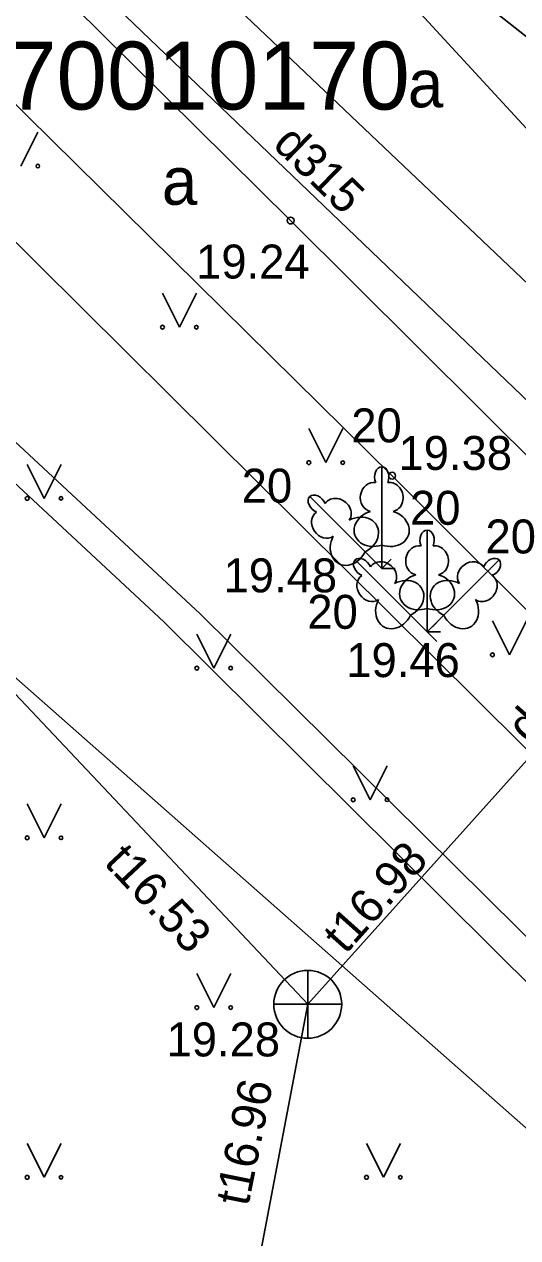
# Model space of a CAD drawing. Extents: x 532933 to 533143, y 328014 to 328163.
# Drawn here: x 533014.71 to 533021.98, y 328109.11 to 328126.98 of the extents above; entities that cross this region are included whole.
import ezdxf

# ---------------------------------------------------------------- set-up
doc = ezdxf.new("R2010")
doc.units = 0
for name, color, linetype in [('APGR_SARK_####_####_#', 7, 'Continuous'), ('CELI_CAPM_####_####_#', 7, 'Continuous'), ('CELI_CMAL_####_####_#', 7, 'Continuous'), ('CELI_CSEG_####_TKST_#', 7, 'Continuous'), ('LKAN_VADP_PAST_####_#', 7, 'Continuous'), ('LKAN_VADP_PAST_TKST_#', 7, 'Continuous'), ('RELJ_AATZ_####_TKST_#', 7, 'Continuous'), ('RELJ_ELEM_####_####_#', 7, 'Continuous'), ('ROBZ_PROJ_####_####_#', 7, 'Continuous'), ('ROBZ_PROJ_####_TKST_#', 7, 'Continuous'), ('ROBZ_UZMR_####_####_#', 7, 'Continuous'), ('SAKK_KKAN_####_####_#', 7, 'Continuous'), ('SAKT_VADV_PKAB_####_#', 7, 'Continuous'), ('SILT_VADP_UDEN_####_#', 7, 'Continuous'), ('SKAN_ELEM_####_####_#', 7, 'Continuous'), ('SKAN_ELEM_PAST_TKST_#', 7, 'Continuous'), ('SKAN_VADP_PAST_####_#', 7, 'Continuous'), ('SKAN_VADP_PAST_TKST_#', 7, 'Continuous'), ('TERT_DIAM_####_TKST_#', 7, 'Continuous'), ('TERT_ELEM_####_####_#', 7, 'Continuous'), ('UDTK_VADP_UDEN_####_#', 7, 'Continuous')]:
    doc.layers.add(name, color=color, linetype=linetype)

msp = doc.modelspace()

# ---------------------------------------------------------------- linework, layer by layer
at = {"layer": 'APGR_SARK_####_####_#'}
msp.add_line((533025.763, 328107.492), (532984.275, 328144.093), dxfattribs=at)
at = {"layer": 'CELI_CAPM_####_####_#'}
msp.add_lwpolyline([(533027.507, 328110.598), (533028.305, 328111.541), (533028.663, 328113.007), (533027.956, 328114.821), (533018.633, 328124.092), (533008.536, 328134.073), (533000, 328142.512)], dxfattribs=at)
at = {"layer": 'CELI_CMAL_####_####_#'}
msp.add_lwpolyline([(533000, 328140.228), (533009.371, 328130.936), (533020.128, 328120.334), (533028.429, 328112.049)], dxfattribs=at)
at = {"layer": 'LKAN_VADP_PAST_####_#'}
msp.add_lwpolyline([(533000, 328144.172), (533010.252, 328132.804), (533025.892, 328117.826), (533035.077, 328109.135), (533038.53, 328105.77)], dxfattribs=at)
at = {"layer": 'RELJ_ELEM_####_####_#'}
for centre in [(533018.633, 328124.092), (533020.128, 328120.334)]:
    msp.add_circle(centre, 0.05, dxfattribs=at)
at = {"layer": 'ROBZ_PROJ_####_####_#'}
msp.add_line((533025.763, 328107.492), (532984.275, 328144.093), dxfattribs=at)
at = {"layer": 'ROBZ_UZMR_####_####_#'}
msp.add_line((532984.275, 328144.093), (533025.763, 328107.492), dxfattribs=at)
at = {"layer": 'SAKK_KKAN_####_####_#'}
msp.add_lwpolyline([(533000, 328138.237), (533026.568, 328111.881), (533036.477, 328102.895)], dxfattribs=at)
at = {"layer": 'SAKT_VADV_PKAB_####_#'}
msp.add_lwpolyline([(533043.676, 328109.828), (532992.415, 328150.168)], dxfattribs=at)
at = {"layer": 'SILT_VADP_UDEN_####_#'}
for points in [[(533004.853, 328045.947), (533019.384, 328034.966), (533019.749, 328035.185), (533031.003, 328047.839), (533031.356, 328048.225), (533031.335, 328048.654), (533025.793, 328053.779), (533025.755, 328054.215), (533035.838, 328064.377), (533036.105, 328064.808), (533033.176, 328075.216), (533032.836, 328076.021), (533015.446, 328091.145), (533015.462, 328091.585), (533029.065, 328106.172), (533029.033, 328106.692), (533017.302, 328118.3), (533000, 328134.38)], [(533000, 328133.784), (533016.764, 328118.182), (533028.476, 328106.559), (533028.508, 328106.039), (533014.85, 328091.596), (533014.892, 328091.077), (533032.527, 328075.724), (533032.689, 328075.239), (533035.542, 328065.283), (533035.311, 328064.711), (533024.98, 328054.226), (533025.028, 328053.821), (533027.938, 328051.227), (533030.653, 328048.689), (533030.642, 328048.162), (533019.754, 328035.526), (533019.215, 328035.483), (533005.473, 328047.022)]]:
    msp.add_lwpolyline(points, dxfattribs=at)
at = {"layer": 'SKAN_ELEM_####_####_#'}
for p, q in [((533018.885, 328112.048), (533018.885, 328113.048)), ((533018.385, 328112.548), (533019.385, 328112.548))]:
    msp.add_line(p, q, dxfattribs=at)
msp.add_circle((533018.885, 328112.548), 0.5, dxfattribs=at)
at = {"layer": 'SKAN_VADP_PAST_####_#'}
for points in [[(533001.531, 328130.94), (533018.885, 328112.548), (533025.52, 328119.937), (533007.233, 328137.297), (533000, 328145.658)], [(533018.885, 328112.548), (533015.334, 328093.891), (533000, 328076.986)]]:
    msp.add_lwpolyline(points, dxfattribs=at)
at = {"layer": 'TERT_ELEM_####_####_#'}
for p, q in [((533014.658, 328124.894), (533014.908, 328125.394)), ((533016.745, 328123.021), (533016.995, 328122.521)), ((533016.995, 328122.521), (533017.245, 328123.021)), ((533018.902, 328121.027), (533019.152, 328120.527)), ((533019.152, 328120.527), (533019.402, 328121.027)), ((533014.75, 328120.5), (533015, 328120)), ((533015, 328120), (533015.25, 328120.5)), ((533019.729, 328119.211), (533019.975, 328118.966)), ((533019.975, 328119.313), (533019.975, 328118.966)), ((533019.975, 328118.966), (533020.116, 328119.107)), ((533019.975, 328118.966), (533020.175, 328118.966)), ((533020.643, 328118.38), (533020.643, 328118.033)), ((533020.398, 328118.278), (533020.643, 328118.033)), ((533020.889, 328118.278), (533020.643, 328118.033)), ((533020.643, 328118.033), (533020.785, 328118.174)), ((533021.607, 328118.195), (533021.857, 328117.695)), ((533021.857, 328117.695), (533022.107, 328118.195)), ((533017.25, 328118), (533017.5, 328117.5)), ((533017.5, 328117.5), (533017.75, 328118)), ((533020.643, 328118.033), (533020.843, 328118.033)), ((533020.643, 328118.033), (533020.785, 328117.891)), ((533019.554, 328116.061), (533019.804, 328115.561)), ((533019.804, 328115.561), (533020.054, 328116.061)), ((533014.75, 328115.5), (533015, 328115)), ((533015, 328115), (533015.25, 328115.5)), ((533017.25, 328113), (533017.5, 328112.5)), ((533017.5, 328112.5), (533017.75, 328113)), ((533014.75, 328110.5), (533015, 328110)), ((533015, 328110), (533015.25, 328110.5)), ((533019.75, 328110.5), (533020, 328110)), ((533020, 328110), (533020.25, 328110.5))]:
    msp.add_line(p, q, dxfattribs=at)
for points in [[(533019.975, 328120.466), (533019.975, 328119.313)], [(533020.064, 328120.233), (533020.063, 328120.234)], [(533018.914, 328120.026), (533019.729, 328119.211)], [(533019.141, 328119.925), (533019.14, 328119.925)], [(533020.643, 328119.533), (533020.643, 328118.38)], [(533020.733, 328119.301), (533020.732, 328119.301)], [(533019.583, 328119.094), (533020.398, 328118.278)], [(533021.704, 328119.094), (533020.889, 328118.278)], [(533019.81, 328118.993), (533019.809, 328118.993)], [(533021.603, 328118.866), (533021.603, 328118.867)]]:
    msp.add_lwpolyline(points, dxfattribs=at)
for centre, radius in [((533014.908, 328124.894), 0.0263), ((533016.744, 328122.521), 0.028), ((533017.244, 328122.521), 0.0263), ((533018.901, 328120.527), 0.028), ((533019.401, 328120.527), 0.0263), ((533014.75, 328120), 0.028), ((533015.25, 328120), 0.0263), ((533021.606, 328117.695), 0.028), ((533017.25, 328117.5), 0.028), ((533017.75, 328117.5), 0.0263), ((533019.554, 328115.561), 0.028), ((533020.054, 328115.561), 0.0263), ((533014.75, 328115), 0.028), ((533015.25, 328115), 0.0263), ((533017.25, 328112.5), 0.028), ((533017.75, 328112.5), 0.0263), ((533014.75, 328110), 0.028), ((533015.25, 328110), 0.0263), ((533019.75, 328110), 0.028), ((533020.25, 328110), 0.0263)]:
    msp.add_circle(centre, radius, dxfattribs=at)
for centre, major_axis, ratio, start_param, end_param in [((533019.975, 328120.316), (0, -0.15), 0.707107, 3.14537, 5.287485), ((533019.974, 328120.316), (0, -0.15), 0.707107, 0.995701, 3.137816), ((533019.846, 328120.021), (-0.039, -0.212), 0.861323, 3.141593, 6.283185), ((533020.103, 328120.021), (0.039, -0.212), 0.861323, 0, 3.141593), ((533019.02, 328119.921), (0.106, -0.106), 0.707107, 3.14537, 5.287485), ((533019.02, 328119.92), (0.106, -0.106), 0.707107, 0.995701, 3.137816), ((533019.319, 328119.803), (0.178, -0.123), 0.861323, 0, 3.141593), ((533019.138, 328119.621), (0.123, -0.178), 0.861323, 3.141593, 6.283185), ((533019.619, 328119.448), (-0.284, -0.15), 0.814445, 1.531171, 4.712389), ((533019.885, 328119.559), (0.307, 0.095), 0.814445, 1.570796, 4.752015), ((533020.064, 328119.559), (-0.307, 0.095), 0.814445, 1.531171, 4.712389), ((533020.644, 328119.383), (0, -0.15), 0.707107, 3.14537, 5.287485), ((533020.643, 328119.383), (0, -0.15), 0.707107, 0.995701, 3.137816), ((533019.492, 328119.322), (0.15, 0.284), 0.814445, 1.570796, 4.752015), ((533020.515, 328119.088), (-0.039, -0.212), 0.861323, 3.141593, 6.283185), ((533020.771, 328119.088), (0.039, -0.212), 0.861323, 0, 3.141593), ((533019.689, 328118.988), (0.106, -0.106), 0.707107, 3.14537, 5.287485), ((533019.688, 328118.987), (0.106, -0.106), 0.707107, 0.995701, 3.137816), ((533019.988, 328118.87), (0.178, -0.123), 0.861323, 0, 3.141593), ((533021.299, 328118.87), (-0.178, -0.123), 0.861323, 3.141593, 6.283185), ((533021.598, 328118.987), (-0.106, -0.106), 0.707107, 3.14537, 5.287485), ((533021.598, 328118.988), (-0.106, -0.106), 0.707107, 0.995701, 3.137816), ((533019.806, 328118.688), (0.123, -0.178), 0.861323, 3.141593, 6.283185), ((533020.554, 328118.626), (0.307, 0.095), 0.814445, 1.570796, 4.752015), ((533020.733, 328118.626), (-0.307, 0.095), 0.814445, 1.531171, 4.712389), ((533021.48, 328118.688), (-0.123, -0.178), 0.861323, 0, 3.141593), ((533020.287, 328118.515), (-0.284, -0.15), 0.814445, 1.531171, 4.712389), ((533020.999, 328118.515), (0.284, -0.15), 0.814445, 1.570796, 4.752015), ((533020.161, 328118.389), (0.15, 0.284), 0.814445, 1.570796, 4.752015), ((533021.126, 328118.389), (-0.15, 0.284), 0.814445, 1.531171, 4.712389)]:
    msp.add_ellipse(centre, major_axis=major_axis, ratio=ratio, start_param=start_param, end_param=end_param, dxfattribs=at)
at = {"layer": 'UDTK_VADP_UDEN_####_#'}
msp.add_line((533009.846, 328138.784), (533026.302, 328120.883), dxfattribs=at)

# ---------------------------------------------------------------- texts
at = {"layer": 'CELI_CSEG_####_TKST_#'}
for p in [(533020.36, 328125.76), (533016.735, 328124.325)]:
    msp.add_text('a', height=0.7, dxfattribs=at).set_placement(p)
at = {"layer": 'LKAN_VADP_PAST_TKST_#'}
msp.add_text('d315', height=0.5, rotation=315.8258, dxfattribs=at).set_placement((533018.352, 328125.192))
at = {"layer": 'RELJ_AATZ_####_TKST_#'}
for s, p in [(' 19.24', (533017.054, 328123.238)), (' 19.38', (533020.036, 328120.419)), (' 19.48', (533017.459, 328118.616)), (' 19.46', (533019.267, 328117.368))]:
    msp.add_text(s, height=0.5, dxfattribs=at).set_placement(p)
at = {"layer": 'ROBZ_PROJ_####_TKST_#'}
msp.add_text('80170010170', height=1, dxfattribs=at).set_placement((533012.208, 328125.727))
at = {"layer": 'SKAN_ELEM_PAST_TKST_#'}
msp.add_text(' 19.28', height=0.5, dxfattribs=at).set_placement((533016.618, 328111.781))
at = {"layer": 'SKAN_VADP_PAST_TKST_#'}
for s, rotation, p in [('d200', 48.1753, (533022.15, 328116.363)), ('t16.53', 313.1117, (533015.868, 328114.623)), ('t16.98', 48.1753, (533019.442, 328113.275)), ('t16.96', 78.6418, (533018.008, 328109.561))]:
    msp.add_text(s, height=0.5, rotation=rotation, dxfattribs=at).set_placement(p)
at = {"layer": 'TERT_DIAM_####_TKST_#'}
for p in [(533019.527, 328120.825), (533017.912, 328119.937), (533020.392, 328119.611), (533021.504, 328119.189), (533018.879, 328118.079)]:
    msp.add_text('20', height=0.5, dxfattribs=at).set_placement(p)

doc.saveas('drawing.dxf')
